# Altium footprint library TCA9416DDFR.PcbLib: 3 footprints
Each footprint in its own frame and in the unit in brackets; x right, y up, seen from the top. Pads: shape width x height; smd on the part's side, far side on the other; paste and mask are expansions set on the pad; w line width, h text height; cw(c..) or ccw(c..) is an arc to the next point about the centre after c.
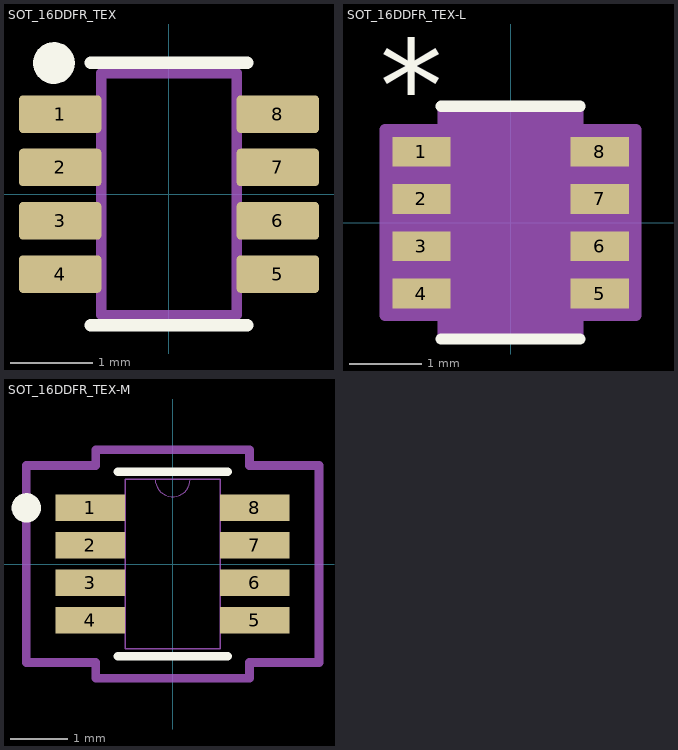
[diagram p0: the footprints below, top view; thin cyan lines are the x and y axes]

## SOT_16DDFR_TEX [mil]
pads (8):
  rrect20% 39.5x18 smd paste+0 mask+0: 1(-52.25,38.38) 2(-52.25,12.79) 3(-52.25,-12.79) 4(-52.25,-38.38) 5(52.25,-38.38) 6(52.25,-12.79) 7(52.25,12.79) 8(52.25,38.38)
Top Overlay:
  circle w10: c-55.24,62.93 r5
  lines w6: -37.5,-63 37.5,-63 ; -37.5,63 37.5,63
Top M5 Assembly Top/M6 Assembly Bottom:
  lines w5: -32.5,-58 32.5,-58 32.5,58 -32.5,58 -32.5,-58
  text ".Designator" at -22.63,18.34 h30
3D body "SOT_16DDFR_TEX.step": height 43.11, standoff 0, extent -57.99,-57.99 57.99,57.99

## SOT_16DDFR_TEX-L [mil]
pads (8):
  rect 31.5x16 smd paste+0 mask+0: 1(-48.25,38.38) 2(-48.25,12.79) 3(-48.25,-12.79) 4(-48.25,-38.38) 5(48.25,-38.38) 6(48.25,-12.79) 7(48.25,12.79) 8(48.25,38.38)
Top Overlay:
  lines w6: -37.5,-63 37.5,-63 ; -37.5,63 37.5,63
  text "*" at -70.75,49.38 h50
Top M13 Component Bodies Top/M14 Component Bodies Bottom:
  lines w0: -12,58 ccw(c0,58) 12,58
  lines w1: -58,-46.38 -58,-30.39 -32.5,-30.39 -32.5,-46.38 -58,-46.38 ; -58,-20.8 -58,-4.79 -32.5,-4.79 -32.5,-20.8 -58,-20.8 ; -58,4.79 -58,20.8 -32.5,20.8 -32.5,4.79 -58,4.79 ; -58,30.39 -58,46.38 -32.5,46.38 -32.5,30.39 -58,30.39 ; -32.5,-58 32.5,-58 32.5,58 -32.5,58 -32.5,-58 ; 32.5,-46.38 32.5,-30.39 58,-30.39 58,-46.38 32.5,-46.38 ; 32.5,-20.8 32.5,-4.79 58,-4.79 58,-20.8 32.5,-20.8 ; 32.5,4.79 32.5,20.8 58,20.8 58,4.79 32.5,4.79 ; 32.5,30.39 32.5,46.38 58,46.38 58,30.39 32.5,30.39
  text "*" at -30,5 h50
Top M15 Courtyards Top/M16 Courtyards Bottom (Mech15):
  region: -36.5,-50.38 -68,-50.38 -68,50.38 -36.5,50.38 -36.5,62 36.5,62 36.5,50.38 68,50.38 68,-50.38 36.5,-50.38 36.5,-62 -36.5,-62
  lines w6: -68,-50.38 -68,50.38 -36.5,50.38 -36.5,62 36.5,62 36.5,50.38 68,50.38 68,-50.38 36.5,-50.38 36.5,-62 -36.5,-62 -36.5,-50.38 -68,-50.38
3D body "SOT_16DDFR_TEX.step": height 43.11, standoff 0, extent -57.99,-57.99 57.99,57.99

## SOT_16DDFR_TEX-M [mil]
pads (8):
  rect 47.5x18 smd paste+0 mask+0: 1(-56.25,38.38) 2(-56.25,12.79) 3(-56.25,-12.79) 4(-56.25,-38.38) 5(56.25,-38.38) 6(56.25,-12.79) 7(56.25,12.79) 8(56.25,38.38)
Top Overlay:
  circle w10: c-100,38.38 r5
  lines w6: -37.5,-63 37.5,-63 ; -37.5,63 37.5,63
Top M13 Component Bodies Top/M14 Component Bodies Bottom:
  lines w0: -12,58 ccw(c0,58) 12,58
  lines w1: -58,-46.38 -58,-30.39 -32.5,-30.39 -32.5,-46.38 -58,-46.38 ; -58,-20.8 -58,-4.79 -32.5,-4.79 -32.5,-20.8 -58,-20.8 ; -58,4.79 -58,20.8 -32.5,20.8 -32.5,4.79 -58,4.79 ; -58,30.39 -58,46.38 -32.5,46.38 -32.5,30.39 -58,30.39 ; -32.5,-58 32.5,-58 32.5,58 -32.5,58 -32.5,-58 ; 32.5,-46.38 32.5,-30.39 58,-30.39 58,-46.38 32.5,-46.38 ; 32.5,-20.8 32.5,-4.79 58,-4.79 58,-20.8 32.5,-20.8 ; 32.5,4.79 32.5,20.8 58,20.8 58,4.79 32.5,4.79 ; 32.5,30.39 32.5,46.38 58,46.38 58,30.39 32.5,30.39
  text "*" at -30,5 h50
Top M15 Courtyards Top/M16 Courtyards Bottom (Mech15):
  lines w6: -100,-67.39 -100,67.39 -52.5,67.39 -52.5,78 52.5,78 52.5,67.39 100,67.39 100,-67.39 52.5,-67.39 52.5,-78 -52.5,-78 -52.5,-67.39 -100,-67.39
3D body "SOT_16DDFR_TEX.step": height 43.11, standoff 0, extent -57.99,-57.99 57.99,57.99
